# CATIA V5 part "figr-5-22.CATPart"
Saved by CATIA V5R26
Part number: Part1
Bounding box of the stored display mesh (mm): x -50 to 50, y 0 to 90.129, z 0 to 181.346
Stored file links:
  D:\_Deepak\CATIA\CATIA V5-6R2016_Deepak\Resources\Part files\Partfiles\c05_catia_v5_6r2016_prt\figr-5-22.CATPart
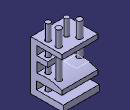
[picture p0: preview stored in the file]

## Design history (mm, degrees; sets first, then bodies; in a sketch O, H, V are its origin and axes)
Set1
  Plane1: type Offset, RefPlane face of Pad1, Offset 44, reversed
  Plane2: type Offset, RefPlane face of Pad1, Offset -46, reversed
Body1 (main body)
  Sketch1 on yz-plane, origin (0, 0, 0), H (0, 1, 0), V (0, 0, 1)
    line L1 (0, 0) -> (90.1292, 0)
    line L2 (90.1292, 0) -> (90.1292, 17.5473)
    line L3 (90.1292, 17.5473) -> (15.9521, 17.5473)
    line L4 (15.9521, 17.5473) -> (15.9521, 39.2532)
    line L5 (15.9521, 39.2532) -> (86.4281, 39.2532)
    line L6 (86.4281, 39.2532) -> (86.4281, 51.1017)
    arc A1 centre (39.4717, -66.63) radius 126.7503 from (86.4281, 51.1017) to (16.1896, 57.9637) ccw
    line L7 (16.1896, 57.9637) -> (16.1896, 86.2043)
    line L8 (16.1896, 86.2043) -> (46.6673, 86.2043)
    line L9 (46.6673, 86.2043) -> (46.6673, 100.2494)
    line L10 (46.6673, 100.2494) -> (16.1896, 100.2494)
    point P12 (16.1896, 100.2494)
    line L11 (16.1896, 100.2494) -> (16.1896, 124.3269)
    line L12 (16.1896, 124.3269) -> (86.4281, 124.3269)
    point P14 (86.4281, 124.3269)
    line L13 (86.4281, 124.3269) -> (86.4281, 137.3459)
    line L14 (86.4281, 137.3459) -> (0, 137.3459)
    point P16 (0, 137.3459)
    line L15 (0, 137.3459) -> (0, 0)
    horizontal: L1 H, L3 H, L5 H, L8 H, L10 H, L12 H, L14 H
    vertical: L2 V, L4 V, L6 V, L7 V, L9 V, L11 V, L13 V, L15 V
    coincidence: P12 L7, P14 L6, P16 V
  Pad1: profile Sketch1, direction (1, 0, 0), length 50, mirrored extent
  Sketch2 on Plane1, origin (0, 0, 181.3459), H (1, 0, 0), V (0, 1, 0)
    circle A1 centre (33.9095, 61.631) radius 7.5057
  Pad2: profile Sketch2, direction (0, 0, -1), up to face of Pad1
  Sketch3 on Plane1, origin (0, 0, 181.3459), H (1, 0, 0), V (0, -1, 0)
    circle A1 centre (-16.2674, -69.1948) radius 7.8522
  Pad3: profile Sketch3, direction (0, 0, -1), up to Plane2
  Sketch4 on Plane1, origin (0, 0, 181.3459), H (1, 0, 0), V (0, -1, 0)
    circle A1 centre (34.469, -32.4508) radius 7.1315
  Pad4: profile Sketch4, direction (0, 0, -1), up to the existing solid (limit type 3)
  Sketch5 on Plane1, origin (0, 0, 181.3459), H (1, 0, 0), V (0, -1, 0)
    circle A1 centre (-3.1833, -46.4863) radius 6.6131
  Pad5: profile Sketch5, direction (0, 0, -1), up to the existing solid (limit type 2)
